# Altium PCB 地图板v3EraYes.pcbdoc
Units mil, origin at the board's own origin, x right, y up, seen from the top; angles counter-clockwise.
Board outline 6585 x 4935 mil, 2 copper layers (Top Layer, Bottom Layer); 79 components, 11 nets, 236 pads, 2 vias.
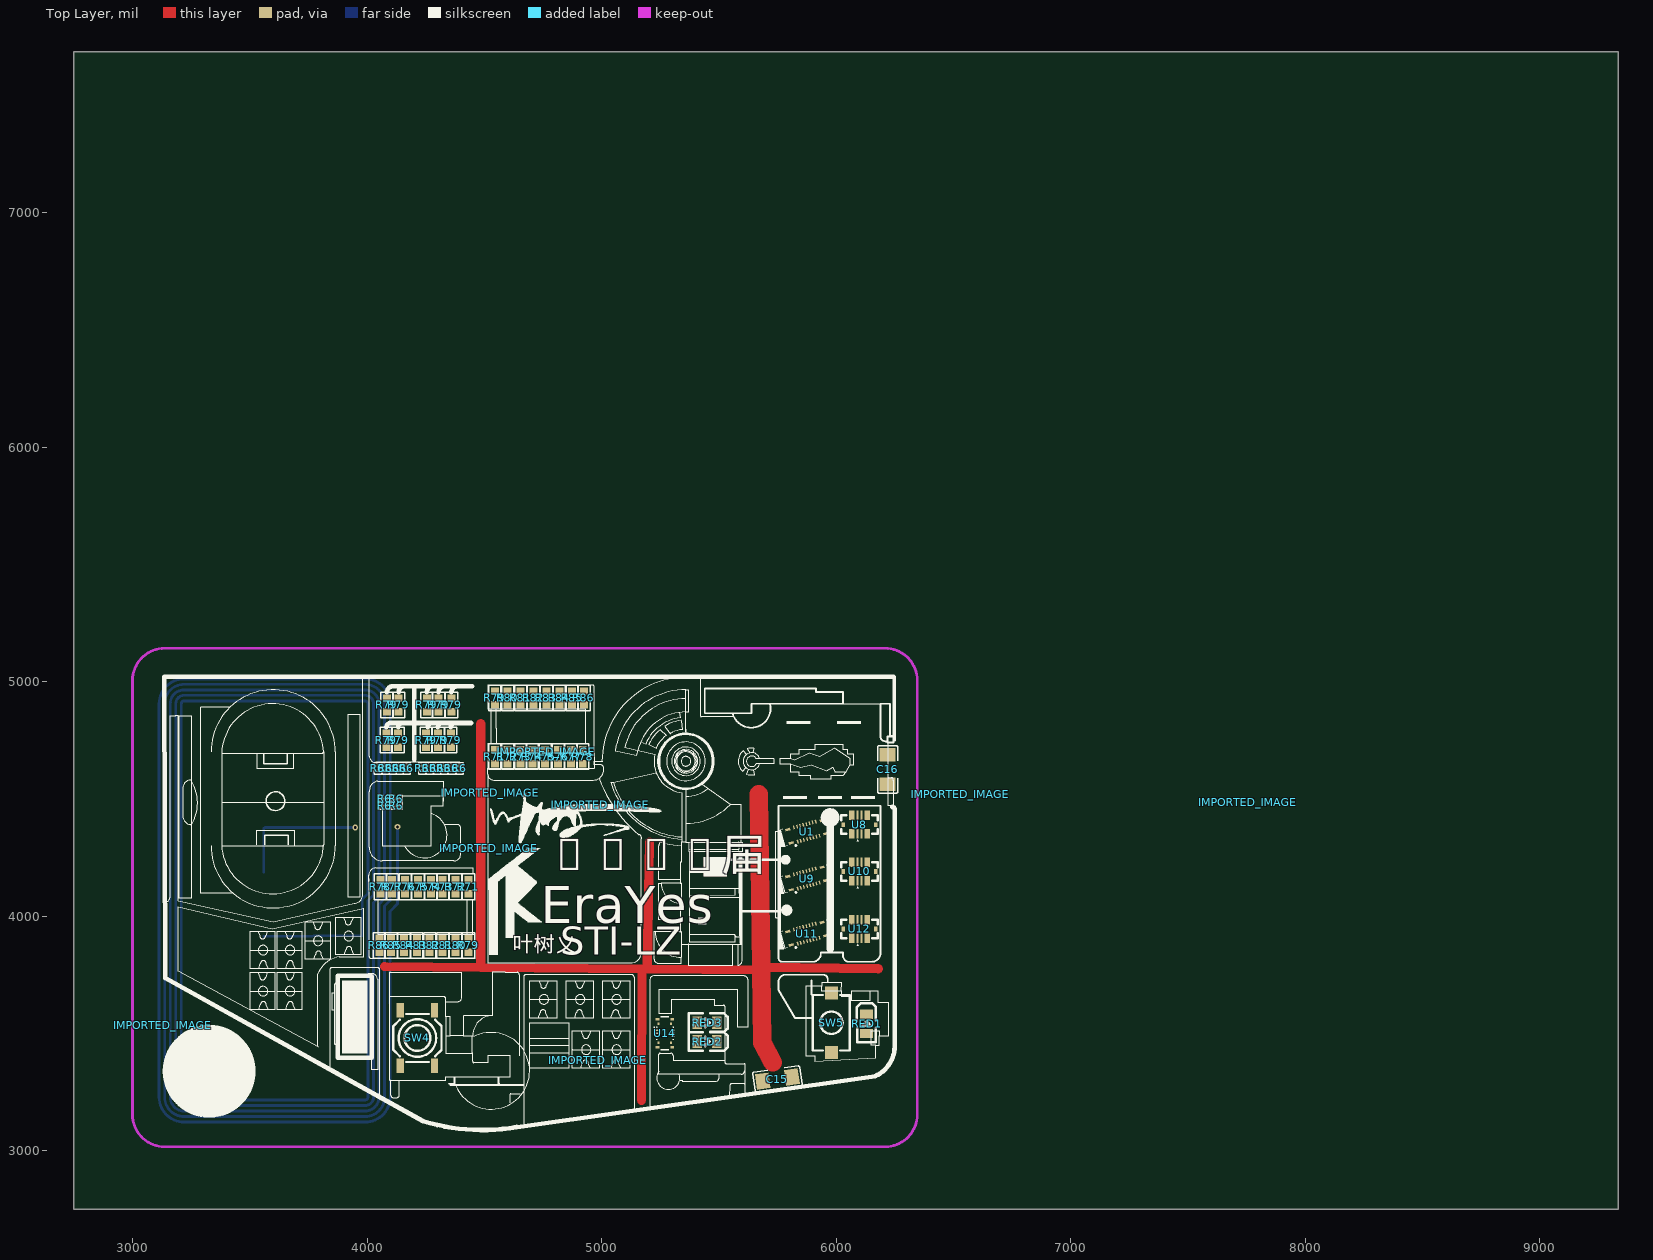
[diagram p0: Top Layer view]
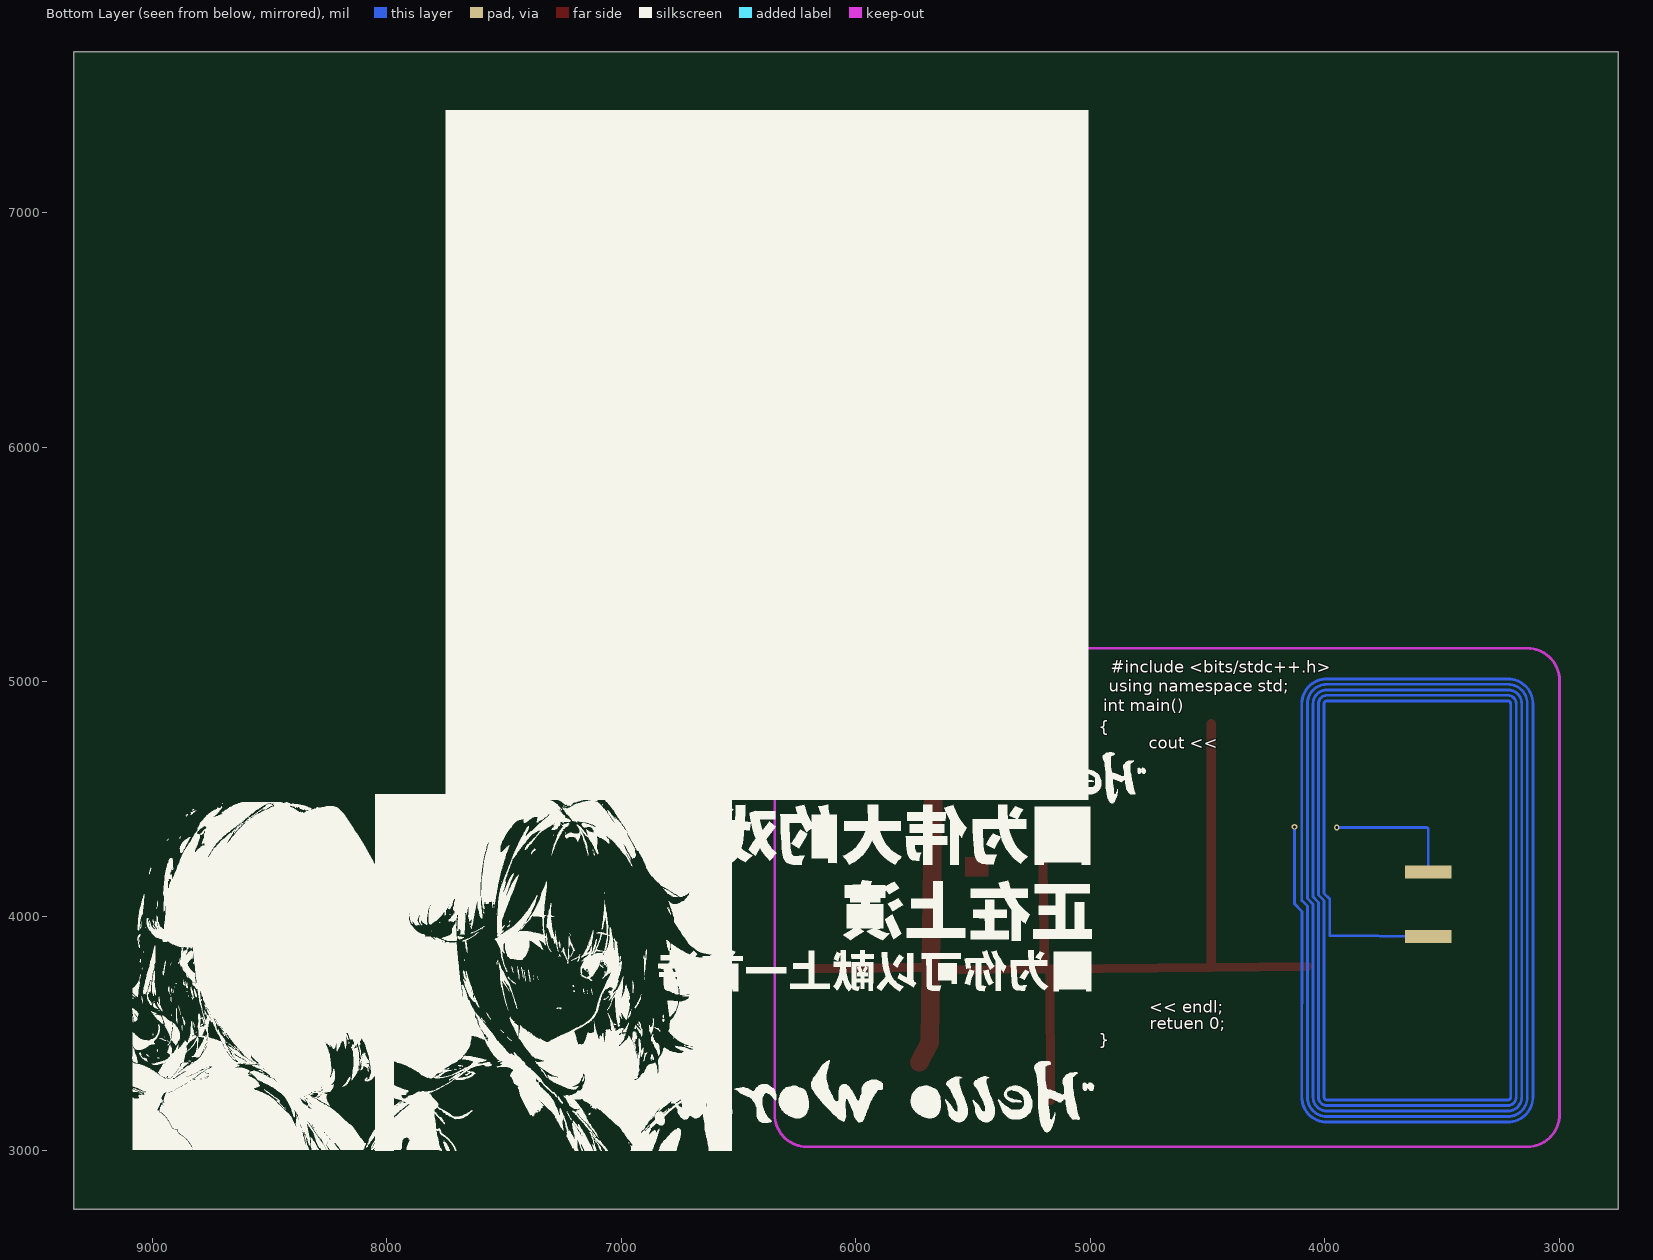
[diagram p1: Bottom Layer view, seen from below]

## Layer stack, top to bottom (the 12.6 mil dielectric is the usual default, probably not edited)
Top Layer: signal copper (thickness not stored)
Dielectric: dielectric 12.6, FR-4, Dk 4.8
Bottom Layer: signal copper (thickness not stored)

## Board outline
9335,2750 2750,2750 2750,7685 9335,7685

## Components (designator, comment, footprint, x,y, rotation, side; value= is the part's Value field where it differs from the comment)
C15 "0.1u" C1206 5750,3305 r8 top
C16 "0.1u" C1206 6220,4625 r90 top
IMPORTED_IMAGE "IMPORTED_IMAGE" IMPORTED_IMAGE 3130,3535 r0 top
IMPORTED_IMAGE "IMPORTED_IMAGE" IMPORTED_IMAGE 4520,4290 r0 top
IMPORTED_IMAGE "IMPORTED_IMAGE" IMPORTED_IMAGE 7755,4485 r0 top
IMPORTED_IMAGE "IMPORTED_IMAGE" IMPORTED_IMAGE 4525,4525 r0 top
IMPORTED_IMAGE "IMPORTED_IMAGE" IMPORTED_IMAGE 4995,4475 r0 top
IMPORTED_IMAGE "IMPORTED_IMAGE" IMPORTED_IMAGE 4765,4700 r0 top
IMPORTED_IMAGE "IMPORTED_IMAGE" IMPORTED_IMAGE 6530,4520 r0 top
IMPORTED_IMAGE "IMPORTED_IMAGE" IMPORTED_IMAGE 4985,3385 r0 top
R6 "1k" R0201 4125,4470 r0 top
R6 "1k" R0201 4125,4500 r0 top
R6 "1k" R0201 4075,4470 r0 top
R6 "1k" R0201 4075,4500 r0 top
R6 "1k" R0201 4046.87,4630 r270 top
R6 "1k" R0201 4080,4630 r270 top
R6 "1k" R0201 4110,4630 r270 top
R6 "1k" R0201 4140,4630 r270 top
R6 "1k" R0201 4170,4630 r270 top
R6 "1k" R0201 4235.53,4630 r270 top
R6 "1k" R0201 4267.97,4630 r270 top
R6 "1k" R0201 4300,4630 r270 top
R6 "1k" R0201 4329.96,4630 r270 top
R6 "1k" R0201 4362.39,4630 r270 top
R6 "1k" R0201 4395,4630 r270 top
R71 "1k" R0603 4545,4680 r90 top
R71 "1k" R0603 4432.5,4125 r270 top
R72 "1k" R0603 4600,4680 r90 top
R72 "1k" R0603 4377.5,4125 r270 top
R73 "1k" R0603 4655,4680 r90 top
R73 "1k" R0603 4322.5,4125 r270 top
R74 "1k" R0603 4705,4680 r90 top
R74 "1k" R0603 4272.5,4125 r270 top
R75 "1k" R0603 4760,4680 r90 top
R75 "1k" R0603 4217.5,4125 r270 top
R76 "1k" R0603 4815,4680 r90 top
R76 "1k" R0603 4162.5,4125 r270 top
R77 "1k" R0603 4870,4680 r90 top
R77 "1k" R0603 4107.5,4125 r270 top
R78 "1k" R0603 4920,4680 r90 top
R78 "1k" R0603 4057.5,4125 r270 top
R79 "1k" R0603 4545,4930 r90 top
R79 "1k" R0603 4432.5,3875 r270 top
R79 "1k" R0603 4085,4900 r90 top
R79 "1k" R0603 4135,4900 r90 top
R79 "1k" R0603 4255,4900 r90 top
R79 "1k" R0603 4305,4900 r90 top
R79 "1k" R0603 4360,4900 r90 top
R79 "1k" R0603 4082.5,4750 r90 top
R79 "1k" R0603 4132.5,4750 r90 top
R79 "1k" R0603 4252.5,4750 r90 top
R79 "1k" R0603 4357.5,4750 r90 top
R79 "1k" R0603 4302.5,4750 r90 top
R80 "1k" R0603 4600,4930 r90 top
R80 "1k" R0603 4377.5,3875 r270 top
R81 "1k" R0603 4655,4930 r90 top
R81 "1k" R0603 4322.5,3875 r270 top
R82 "1k" R0603 4710,4930 r90 top
R82 "1k" R0603 4267.5,3875 r270 top
R83 "1k" R0603 4765,4930 r90 top
R83 "1k" R0603 4212.5,3875 r270 top
R84 "1k" R0603 4820,4930 r90 top
R84 "1k" R0603 4157.5,3875 r270 top
R85 "1k" R0603 4875,4930 r90 top
R85 "1k" R0603 4102.5,3875 r270 top
R86 "1k" R0603 4925,4930 r90 top
R86 "1k" R0603 4052.5,3875 r270 top
RED1 "LED0805-R-RD" LED0805-R-RD 6130,3540 r270 top
RED2 "LED0805-R-RD" LED0805-R-RD 5450,3465 r180 top
RED3 "LED0805-R-RD" LED0805-R-RD 5450,3545 r180 top
SW4 "SW-SMD_4P-L5.2-W5.2-P3.70-LS6.4" SW-SMD_4P-L5.2-W5.2-P3.70-LS6.4 4215,3480 r90 top
SW5 "YTS1C0192ABG00" SW-SMD_L6.0-W4.0-LS7.2 5980,3545 r90 top
U1 "CONN-SMD_BM28B0.6-16DS-2-0.35V-51" CONN-SMD_BM28B0.6-16DS-2-0.35V-51 5875,4360 r15 top
U8 "CONN-SMD_BM25-4P-2-V-51" CONN-SMD_BM25-4P-2-V-51 6100,4390 r0 top
U9 "CONN-SMD_BM28B0.6-16DS-2-0.35V-51" CONN-SMD_BM28B0.6-16DS-2-0.35V-51 5875,4160 r15 top
U10 "CONN-SMD_BM25-4P-2-V-51" CONN-SMD_BM25-4P-2-V-51 6100,4190 r0 top
U11 "CONN-SMD_BM28B0.6-16DS-2-0.35V-51" CONN-SMD_BM28B0.6-16DS-2-0.35V-51 5875,3925 r15 top
U12 "CONN-SMD_BM25-4P-2-V-51" CONN-SMD_BM25-4P-2-V-51 6100,3945 r0 top
U14 "CONN-SMD_AXG106144" CONN-SMD_AXG106144 5270,3500 r270 top

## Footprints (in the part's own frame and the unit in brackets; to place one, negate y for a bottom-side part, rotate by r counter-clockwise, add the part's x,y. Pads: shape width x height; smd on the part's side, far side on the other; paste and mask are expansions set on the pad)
C1206 [mm]
  rect 1.485x1.728 smd paste-100 mask+0.051: 1(-1.593,0) 2(1.593,0)
  silkscreen extent -2.56,-1.09 2.56,1.09
CONN-SMD_AXG106144 [mm]
  rect 0.15x0.35 smd paste+0 mask+0.05: 1(-0.35,-0.845) 2(-0.35,0.845) 3(0,-0.845) 4(0,0.845) 5(0.35,-0.845) 6(0.35,0.845)
  rect 0.3x0.22 smd paste+0 mask+0.05: 7(1.03,0.69) 8(1.03,-0.69) 11(-1.03,-0.69) 12(-1.03,0.69)
  rect 0.28x0.4 smd paste+0 mask+0.05: 9(1.5,0.8) 10(1.5,-0.8) 13(-1.5,-0.8) 14(-1.5,0.8)
  silkscreen extent -1.78,-1.17 1.78,0.89
CONN-SMD_BM25-4P-2-V-51 [mm]
  rect 0.2x1 smd: 1(-0.2,-1) 2(-0.2,1) 3(0.2,-1) 4(0.2,1)
  rect 0.58x1 smd: 5(0.85,-1) 6(0.85,1) 7(-0.85,1) 8(-0.85,-1)
  rect 0.38x0.5 smd: 9(-1.735,0) 10(1.735,0)
  silkscreen extent -1.97,-1.8 1.97,1
CONN-SMD_BM28B0.6-16DS-2-0.35V-51 [mm]
  rect 0.15x0.41 smd: 1(-1.225,-0.795) 2(-0.875,-0.795) 3(-0.525,-0.795) 4(-0.175,-0.795) 5(0.175,-0.795) 6(0.525,-0.795) 7(0.875,-0.795) 8(1.225,-0.795) 9(1.225,0.795) 10(0.875,0.795) 11(0.525,0.795) 12(0.175,0.795) 13(-0.175,0.795) 14(-0.525,0.795) 15(-0.875,0.795) 16(-1.225,0.795)
  rect 0.53x0.31 smd: 17(-1.93,0.745) 18(-1.93,-0.745) 19(1.93,-0.745) 20(1.93,0.745)
  silkscreen extent -2.73,-1.22 2.67,0.9
IMPORTED_IMAGE [mil]
  silkscreen extent 0,-394 394,0
LED0805-R-RD [mm]
  rect 1x1.4 smd: 1(1.05,0) 2(-1.05,0)
  silkscreen extent -2.22,-1.04 1.99,1.01
R0201 [mil]
  rect 11.93x12.76 smd paste-3937.01 mask+2: 1(-9.51,0) 2(9.51,0)
  silkscreen extent -24,-15 24,15
R0603 [mil]
  rect 31.75x34.02 smd paste-3937.01 mask+2: 1(-29.66,0) 2(29.66,0)
  silkscreen extent -55,-26 55,26
SW-SMD_4P-L5.2-W5.2-P3.70-LS6.4 [mm]
  rect 1.58x0.8 smd: 1(-3,1.85) 2(3,1.85) 3(-3,-1.85) 4(3,-1.85)
  silkscreen extent -2.6,-2.6 2.6,2.6
SW-SMD_L6.0-W4.0-LS7.2 [mm]
  rect 1.4x1.4 smd paste+0 mask+0.05: 1(-3.2,0) 2(3.2,0)
  silkscreen extent -3,-2 3,2

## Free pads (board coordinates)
  rect 196.85x55.12 smd far side paste+0 mask-196.85: 11(3560,3912.71) 11(3560,4187.71)

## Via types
v1: diameter 24, hole 12, Top Layer to Bottom Layer, 2 vias

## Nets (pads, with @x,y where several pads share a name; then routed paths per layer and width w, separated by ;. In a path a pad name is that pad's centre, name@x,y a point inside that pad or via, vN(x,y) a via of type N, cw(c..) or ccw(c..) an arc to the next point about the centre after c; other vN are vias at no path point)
C5_1: C15.1 C16.1
C5_2: C15.2 C16.2
R3_1: R71.1 R72.1 R73.1 R74.1 R75.1 R76.1 R77.1 R78.1 R79.1 R80.1 R81.1 R82.1 R83.1 R84.1 R85.1 R86.1
R3_2: R71.2 R72.2 R73.2 R74.2 R75.2 R76.2 R77.2 R78.2 R79.2 R80.2 R81.2 R82.2 R83.2 R84.2 R85.2 R86.2
R6_1: R6.1
R6_2: R6.2
S$48780: pad.11@3560,3912.71 | length 1417.4
  Bottom Layer w12: pad.11@3560,3912.71 3980,3917.71 3980,4072.71 4003.8,4096.51 4003.8,4905.21
S$48796: pad.11@3560,4187.71 | length 950.6
  Bottom Layer w12.01: pad.11@3560,4187.71 3560,4372.71 3565,4377.71 v1(3950,4377.71) ; 4097.45,4019.95 4130,4052.49 v1(4130,4380)
SW1_1: SW5.1
SW1_2: SW5.2
"": RED1.1 RED1.2 RED2.1 RED2.2 RED3.1 RED3.2 SW4.1 SW4.2 SW4.3 SW4.4 U1.1 U1.2 U1.3 U1.4 U1.5 U1.6 U1.7 U1.8 U1.9 U1.10 U1.11 U1.12 U1.13 U1.14 U1.15 U1.16 U1.17 U1.18 U1.19 U1.20 U8.1 U8.2 U8.3 U8.4 U8.5 U8.6 U8.7 U8.8 U8.9 U8.10 U9.1 U9.2 U9.3 U9.4 U9.5 U9.6 U9.7 U9.8 U9.9 U9.10 U9.11 U9.12 U9.13 U9.14 U9.15 U9.16 U9.17 U9.18 U9.19 U9.20 U10.1 U10.2 U10.3 U10.4 U10.5 U10.6 U10.7 U10.8 U10.9 U10.10 U11.1 U11.2 U11.3 U11.4 U11.5 U11.6 U11.7 U11.8 U11.9 U11.10 U11.11 U11.12 U11.13 U11.14 U11.15 U11.16 U11.17 U11.18 U11.19 U11.20 U12.1 U12.2 U12.3 U12.4 U12.5 U12.6 U12.7 U12.8 U12.9 U12.10 U14.1 U14.2 U14.3 U14.4 U14.5 U14.6 U14.7 U14.8 U14.9 U14.10 U14.11 U14.12 U14.13 U14.14 | length 30897.1
  Top Layer w39.37: 4075,3785 4485.13,3781.1 ; 4485,4820 4485.13,3781.1 ; 5170,3215 5172.44,3774.56 ; 5195,3785 5205,4315 ; 5680.44,3781.9 6180,3775 ; 5680.62,3769.72 5172.44,3774.56 ; 4485.13,3781.1 5172.44,3774.56
  Top Layer w78.74: 5670,4520 5680.44,3781.9 5680.62,3769.72 5685,3460 5730.5,3375.51
  Bottom Layer w12: 4003.83,4905.3 ccw(c3991.83,4905.3) 3991.83,4917.3 3220,4917.3 ccw(c3220.09,4905.39) 3208.19,4905.3 3208.19,3227.71 ccw(c3220,3227.71) 3220,3215.9 3991.83,3215.9 ccw(c3991.92,3227.81) 4003.83,3227.71 4003.83,4066.3 4027.83,4090.3 4027.83,4905.3 ccw(c3991.83,4905.3) 3991.83,4941.3 3220,4941.3 ccw(c3220.28,4905.58) 3184.57,4905.29 3184.57,3227.71 ccw(c3220,3227.71) 3220,3192.28 3991.83,3192.28 ccw(c3992.11,3228) 4027.83,3227.71 4027.83,4058.42 4050.83,4082.3 4050.83,4905.3 ccw(c3991.83,4905.3) 3991.83,4964.3 3220,4964.3 ccw(c3219.97,4905.27) 3160.95,4905.3 3160.95,3227.71 ccw(c3220,3227.71) 3220,3168.66 3991.83,3168.66 ccw(c3991.8,3227.68) 4050.83,3227.71 4050.83,4050.55 4074.83,4074.3 4074.83,4905.3 ccw(c3991.83,4905.3) 3991.83,4988.3 3220,4988.3 ccw(c3220.16,4905.46) 3137.32,4905.29 3137.32,3227.71 ccw(c3220,3227.71) 3220,3145.04 3991.83,3145.04 ccw(c3991.99,3227.87) 4074.83,3227.71 4074.83,4042.67 4098.83,4066.3 4098.83,4905.3 ccw(c3992.33,4904.8) 3991.83,5011.3 3220,5011.3 ccw(c3219.85,4905.15) 3113.7,4905.29 3113.7,3227.71 ccw(c3220,3227.71) 3220,3121.41 3991.83,3121.41 ccw(c3992.18,3228.06) 4098.83,3227.71 4097.44,4019.97

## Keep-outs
Board Outline Layer:
  lines w11.81 net "": 3000,3153.82 ccw(c3137.8,3153.82) 3137.8,3016.02 6208.66,3016.02 ccw(c6208.65,3153.82) 6346.45,3153.82 6346.45,5004.2 ccw(c6208.65,5004.2) 6208.65,5142 3137.8,5142 ccw(c3137.8,5004.2) 3000,5004.2 3000,3153.82

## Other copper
Top Layer:
  region net "": 5535,4170 5535,4250 5435,4250 5435,4170

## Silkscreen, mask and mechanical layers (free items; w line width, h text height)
Top Silkscreen Layer:
  drawing of 749 lines, arcs and shapes, not listed
  text "2025届" at 4770.83,4195.08 h135.94
  text "EraYes" at 4740,3970 h157.48
  text "叶树义" at 4620.08,3847.34 h66.9
  text "STI-LZ" at 4825,3835 h120
Bottom Silkscreen Layer:
  region net "": 5010,4495 7750,4495 7750,7435 5010,7435
  text "#include <bits/stdc++.h>" at 4913.51,5037.48 h51.1
  text "using namespace std;" at 4922.49,4957.48 h51.1
  text "int main()" at 4944.93,4872.48 h51.1
  text "{" at 4965,4782.29 h51.47
  text "cout <<" at 4751.66,4712.48 h51.1
  text "<< endl;" at 4749.42,3587.48 h51.1
  text "retuen 0;" at 4747.17,3517.48 h51.1
  text "}" at 4965,3447.29 h51.47
Bottom Solder Mask Layer:
  region net "": 3465,4157.71 3655,4157.71 3655,4212.71 3465,4212.71
  region net "": 3465,3887.71 3655,3887.71 3655,3942.71 3465,3942.71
